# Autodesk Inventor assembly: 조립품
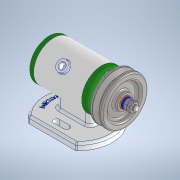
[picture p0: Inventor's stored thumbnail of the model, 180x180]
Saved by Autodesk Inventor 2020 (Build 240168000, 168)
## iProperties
Created: 2022-02
Part Number: 조립품
Document SubType Name: Assembly
Designer: 602-08
Author: 602-08
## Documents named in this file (13)
- C:\Users\602-08\Desktop\720206V1023\조립품.iam
- C:\Users\602-08\Desktop\720206V1023\본체.ipt
- C:\Users\602-08\Desktop\720206V1023\뒤커버.ipt
- C:\Users\602-08\Desktop\720206V1023\앞커버.ipt
- C:\Users\602-08\Desktop\720206V1023\축.ipt
- C:\Users\602-08\Desktop\720206V1023\베어링 6002.ipt
- C:\Users\602-08\Desktop\720206V1023\키 3 x 3 x 12.ipt
- C:\Users\602-08\Desktop\720206V1023\오일 실 15 x 25 x 7.ipt
- C:\Users\602-08\Desktop\720206V1023\V벨트풀리.ipt
- C:\Users\602-08\Desktop\720206V1023\너트 M8.ipt
- C:\Users\602-08\Desktop\720206V1023\평와셔 8 x 17.ipt
- C:\Users\602-08\Desktop\720206V1023\스프링와셔 8.ipt
- C:\Users\602-08\Desktop\720206V1023\볼트 M4 x 10.ipt
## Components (1 placed, 1 different names)
1. V벨트풀리:1
